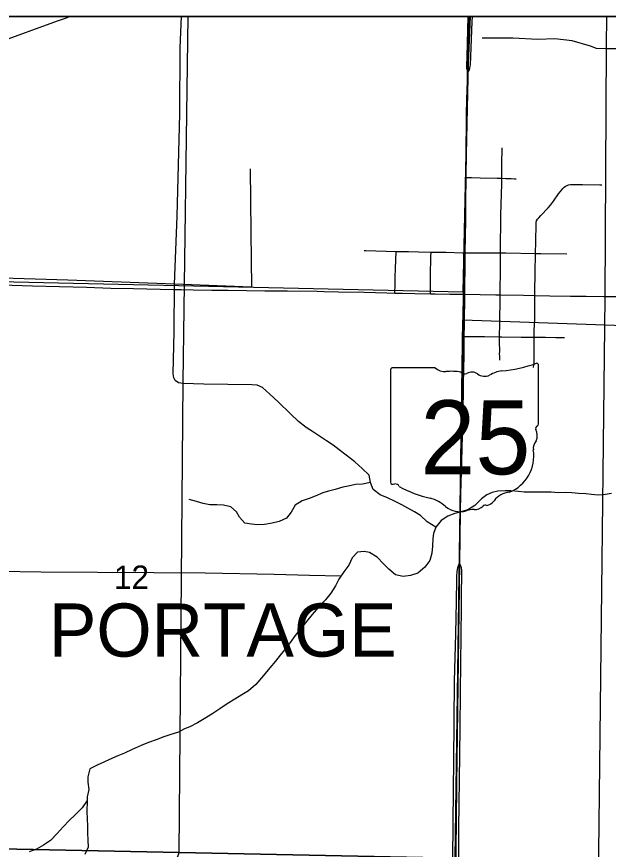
# Model space of a CAD drawing. Extents: x 0 to 39.4, y 0 to 22.
# Drawn here: x 4.625 to 5.679, y 19.416 to 20.9 of the extents above; entities that cross this region are included whole.
import ezdxf

# ---------------------------------------------------------------- set-up
doc = ezdxf.new("R2010")
doc.units = 0
for name, color, linetype in [('Default', 7, 'Continuous'), ('GM_X_City_Street', 7, 'Continuous'), ('GM_X_Corporation_Text', 7, 'Continuous'), ('GM_X_Interstate_Route', 7, 'Continuous'), ('GM_X_Major_River', 7, 'Continuous'), ('GM_X_Minor_River', 7, 'Continuous'), ('GM_X_Rail_Line', 7, 'Continuous'), ('GM_X_Section', 7, 'Continuous'), ('GM_X_Section_Text', 7, 'Continuous'), ('GM_X_State_Location', 7, 'Continuous'), ('GM_X_State_Route', 7, 'Continuous'), ('GM_X_State_Shield', 7, 'Continuous'), ('GM_X_Township_Road', 7, 'Continuous'), ('SH_Data', 7, 'Continuous')]:
    doc.layers.add(name, color=color, linetype=linetype)

msp = doc.modelspace()

# ---------------------------------------------------------------- linework, layer by layer
at = {"layer": 'Default'}
for points in [[(5.4307, 20.9), (4.4171, 20.9), (4.4054, 20.4323), (5.4199, 20.4099)], [(6.4727, 20.9), (5.4307, 20.9), (5.4199, 20.4099), (5.4196, 20.3595), (6.4661, 20.3227)]]:
    msp.add_lwpolyline(points, close=True, dxfattribs=at)
at = {"layer": 'GM_X_City_Street'}
for points in [[(5.4862, 20.4042), (5.4862, 20.4067), (5.4861, 20.4147), (5.4863, 20.4267), (5.4864, 20.4329), (5.4865, 20.4406), (5.4866, 20.4467), (5.4866, 20.4551), (5.4866, 20.4667), (5.4866, 20.4709), (5.4867, 20.479), (5.4867, 20.4855), (5.4868, 20.4938), (5.4869, 20.5043), (5.4874, 20.5228), (5.4874, 20.529), (5.4874, 20.5382), (5.4875, 20.5411), (5.4875, 20.547), (5.4888, 20.6019), (5.4888, 20.6111), (5.4888, 20.612), (5.4889, 20.6173), (5.4888, 20.6203), (5.4891, 20.6388), (5.4892, 20.646), (5.4893, 20.6573), (5.4894, 20.6663)], [(5.4251, 20.6133), (5.4348, 20.6131), (5.4502, 20.6126), (5.4809, 20.6123), (5.4888, 20.612), (5.4963, 20.6117), (5.5055, 20.6116), (5.5115, 20.6113), (5.5145, 20.6111)], [(5.5479, 20.4032), (5.548, 20.4094), (5.5485, 20.4435), (5.5492, 20.478), (5.5496, 20.4993), (5.5499, 20.5303), (5.5501, 20.5334), (5.5509, 20.5364), (5.5526, 20.539), (5.5546, 20.5413), (5.5587, 20.5459), (5.5717, 20.5592), (5.5756, 20.5639), (5.5813, 20.5712), (5.5901, 20.584), (5.5957, 20.5914), (5.5977, 20.5938), (5.5999, 20.596), (5.6024, 20.5979), (5.6051, 20.5993), (5.608, 20.6003), (5.6111, 20.6008), (5.6173, 20.6012), (5.6328, 20.6012), (5.6638, 20.6004), (5.6669, 20.6004)], [(5.244, 20.4835), (5.247, 20.4835), (5.3007, 20.4818), (5.3073, 20.4817), (5.3225, 20.4815), (5.3407, 20.4812), (5.3629, 20.4806), (5.3669, 20.4806), (5.3897, 20.4801), (5.4189, 20.4794), (5.4236, 20.4793)], [(5.2985, 20.4074), (5.2986, 20.412), (5.2988, 20.418), (5.299, 20.4243), (5.2993, 20.4364), (5.2997, 20.4506), (5.3002, 20.4664), (5.3007, 20.4818)], [(5.3617, 20.4062), (5.3617, 20.4131), (5.3619, 20.4381), (5.3627, 20.4724), (5.3629, 20.4806)], [(5.4236, 20.4793), (5.4518, 20.4792), (5.4709, 20.479), (5.4867, 20.479), (5.4959, 20.4789), (5.5492, 20.478), (5.5583, 20.4778), (5.6047, 20.4774)], [(5.4853, 20.2876), (5.4852, 20.2938), (5.4851, 20.2999), (5.4852, 20.3029), (5.4851, 20.3215), (5.485, 20.327), (5.485, 20.3293), (5.485, 20.3366), (5.4853, 20.3458), (5.4854, 20.3581), (5.4855, 20.3643), (5.4856, 20.3674), (5.486, 20.3859), (5.4862, 20.4042)], [(5.5455, 20.2746), (5.5462, 20.2795), (5.5465, 20.2838), (5.5467, 20.2872), (5.5467, 20.2942), (5.5467, 20.3096), (5.5467, 20.322), (5.5466, 20.3287), (5.5467, 20.3318), (5.5468, 20.3404), (5.5475, 20.3622), (5.5476, 20.3715), (5.5479, 20.4032)], [(5.4217, 20.33), (5.4294, 20.3301), (5.4397, 20.3301), (5.4582, 20.3298), (5.485, 20.3293), (5.4888, 20.3293), (5.5233, 20.3287), (5.5386, 20.3287), (5.5466, 20.3287), (5.5559, 20.3287), (5.5667, 20.3286), (5.5853, 20.3285), (5.5915, 20.3284), (5.6006, 20.3285)]]:
    msp.add_lwpolyline(points, dxfattribs=at)
at = {"layer": 'GM_X_Interstate_Route'}
for points in [[(5.4067, 19.4006), (5.4136, 19.9268), (5.4146, 20.0173), (5.4153, 20.0495), (5.4169, 20.1081), (5.4194, 20.1983), (5.42, 20.2356), (5.4203, 20.2505), (5.4205, 20.2661), (5.4211, 20.3031), (5.4214, 20.3225), (5.4215, 20.3305), (5.4218, 20.3506), (5.4224, 20.4059), (5.4227, 20.4226), (5.423, 20.4505), (5.4233, 20.4799), (5.424, 20.5376), (5.4244, 20.5624), (5.4245, 20.5749), (5.4248, 20.6091), (5.4249, 20.6139), (5.4251, 20.6246), (5.4253, 20.6478), (5.4255, 20.6629), (5.4256, 20.6744), (5.4259, 20.6992), (5.4261, 20.7149), (5.4263, 20.7332), (5.4265, 20.7451), (5.4267, 20.7523), (5.4286, 20.8019), (5.4327, 20.9), (2.1, 20.9)], [(8.9, 20.9), (5.4327, 20.9), (5.4286, 20.8019), (5.4267, 20.7523), (5.4265, 20.7451), (5.4263, 20.7332), (5.4261, 20.7149), (5.4259, 20.6992), (5.4256, 20.6744), (5.4255, 20.6629), (5.4253, 20.6478), (5.4251, 20.6246), (5.4249, 20.6139), (5.4248, 20.6091), (5.4245, 20.5749), (5.4244, 20.5624), (5.424, 20.5376), (5.4233, 20.4799), (5.423, 20.4505), (5.4227, 20.4226), (5.4224, 20.4059), (5.4218, 20.3506), (5.4215, 20.3305), (5.4214, 20.3225), (5.4211, 20.3031), (5.4205, 20.2661), (5.4203, 20.2505), (5.42, 20.2356), (5.4194, 20.1983), (5.4169, 20.1081), (5.4153, 20.0495), (5.4146, 20.0173), (5.4136, 19.9268), (5.4067, 19.4006)]]:
    msp.add_lwpolyline(points, dxfattribs=at)
at = {"layer": 'GM_X_Major_River'}
for points in [[(5.6841, 20.0502), (5.6701, 20.0479), (5.6606, 20.0476), (5.6485, 20.0484), (5.6386, 20.0495), (5.6253, 20.0503), (5.6139, 20.0515), (5.6022, 20.0523), (5.59, 20.0516), (5.5768, 20.0524), (5.5665, 20.0528), (5.5532, 20.0528), (5.5434, 20.0525), (5.529, 20.0525), (5.5187, 20.0541), (5.5051, 20.0552), (5.4952, 20.0553), (5.4819, 20.0545), (5.4717, 20.0519), (5.4622, 20.0478), (5.4526, 20.0406), (5.4409, 20.0288), (5.4283, 20.0213), (5.4161, 20.0175), (5.4051, 20.0149), (5.3926, 20.01), (5.3812, 20.0024), (5.3717, 19.9903), (5.3671, 19.9793), (5.3659, 19.9698), (5.3655, 19.9565), (5.3643, 19.944), (5.3609, 19.9311), (5.3517, 19.919), (5.3392, 19.9084), (5.3262, 19.9042), (5.3133, 19.9024), (5.2997, 19.9051), (5.2876, 19.9154), (5.2785, 19.9249), (5.2668, 19.9367), (5.2535, 19.9451), (5.244, 19.947), (5.2319, 19.9455), (5.2224, 19.9357), (5.2166, 19.9224), (5.2075, 19.9107), (5.1987, 19.8974), (5.193, 19.8856), (5.1842, 19.8727), (5.1747, 19.861), (5.1618, 19.8474), (5.1515, 19.8349), (5.1412, 19.822), (5.1313, 19.8099), (5.121, 19.7973), (5.1119, 19.7848), (5.105, 19.775), (5.0943, 19.7621), (5.086, 19.7515), (5.0757, 19.7394), (5.0643, 19.7257), (5.0509, 19.7102), (5.038, 19.6985), (5.0258, 19.6913), (5.0133, 19.6837), (4.9996, 19.6754), (4.9867, 19.6663), (4.9745, 19.658), (4.9619, 19.6505), (4.9467, 19.6418), (4.9331, 19.6346), (4.9236, 19.6308), (4.9129, 19.6248), (4.8996, 19.621), (4.8871, 19.6165), (4.8734, 19.6112), (4.8597, 19.6067), (4.8464, 19.6014), (4.8309, 19.5943), (4.8168, 19.5875), (4.805, 19.5826), (4.7902, 19.5765), (4.7803, 19.5716), (4.7682, 19.566)], [(4.7682, 19.566), (4.7553, 19.5595), (4.7518, 19.5455), (4.7518, 19.536), (4.7536, 19.5227), (4.7505, 19.5098), (4.7505, 19.503)], [(4.7505, 19.503), (4.7418, 19.4901), (4.7284, 19.4772), (4.7189, 19.4681), (4.7075, 19.4564), (4.6972, 19.4443), (4.685, 19.4321), (4.6725, 19.4234), (4.6603, 19.4166), (4.647, 19.4117)]]:
    msp.add_lwpolyline(points, dxfattribs=at)
at = {"layer": 'GM_X_Minor_River'}
for points in [[(5.0439, 20.2442), (4.9581, 20.2449), (4.9217, 20.2461), (4.913, 20.2477), (4.9073, 20.2519), (4.9047, 20.2561), (4.9039, 20.2633), (4.9057, 20.3389), (4.9063, 20.4236), (4.9105, 20.5443), (4.9156, 20.727), (4.9164, 20.8444), (4.9186, 20.9)], [(6.291, 20.8217), (6.1449, 20.8264), (5.9954, 20.8329), (5.8941, 20.8354), (5.8209, 20.8376), (5.7754, 20.8392), (5.7655, 20.8427), (5.756, 20.8465), (5.7405, 20.8492), (5.7276, 20.8488), (5.7097, 20.8455), (5.6961, 20.8429), (5.6767, 20.8429), (5.6574, 20.843), (5.6471, 20.8472), (5.6142, 20.8568), (5.5831, 20.8607), (5.5531, 20.8592), (5.5083, 20.8616), (5.4541, 20.8614)], [(5.0405, 20.629), (5.0417, 20.5162), (5.0429, 20.4182), (4.9063, 20.4236), (4.7159, 20.4302), (4.5213, 20.4361), (4.4146, 20.4383), (4.3289, 20.4412), (4.1931, 20.4443), (4.1506, 20.4456), (3.8975, 20.4498), (3.7617, 20.4536), (3.6141, 20.4571), (3.4491, 20.4655), (3.4017, 20.4657)], [(5.3717, 19.9903), (5.3561, 19.9998), (5.344, 20.0109), (5.3334, 20.0174), (5.3213, 20.0243), (5.3107, 20.03), (5.2978, 20.0365), (5.2853, 20.0426), (5.2721, 20.048), (5.26, 20.0575), (5.2551, 20.0697), (5.2528, 20.083), (5.24, 20.0951), (5.2271, 20.1066), (5.212, 20.1184), (5.1991, 20.1283), (5.1889, 20.1363), (5.1768, 20.1443), (5.1533, 20.1596), (5.1404, 20.1676), (5.1268, 20.1787), (5.1124, 20.192), (5.0908, 20.2137), (5.0761, 20.2274), (5.0628, 20.2389), (5.0532, 20.2436), (5.0439, 20.2442)], [(2.8819, 20.2127), (2.8805, 20.1337), (2.8805, 20.03), (2.8792, 19.9628), (2.9205, 19.9619), (3.0951, 19.9588), (3.2157, 19.955), (3.3064, 19.9524), (3.3716, 19.9492), (3.4706, 19.947), (3.655, 19.9389), (3.8234, 19.9323), (4.0109, 19.9245), (4.1395, 19.9203), (4.3235, 19.916), (4.4418, 19.9145), (4.6683, 19.9107), (4.8691, 19.9098), (4.9609, 19.9087), (5.0834, 19.9068), (5.1464, 19.9048), (5.2027, 19.9034)], [(5.2551, 20.0697), (5.241, 20.067), (5.2281, 20.0663), (5.2156, 20.0633), (5.2057, 20.0614), (5.1924, 20.0577), (5.1803, 20.0547), (5.17, 20.0513), (5.1563, 20.0456), (5.1461, 20.0415), (5.1332, 20.0374), (5.121, 20.0294), (5.1137, 20.0173), (5.1054, 20.0063), (5.0924, 20.0006), (5.0799, 19.9976), (5.0666, 19.995), (5.0537, 19.9947), (5.0431, 19.9955), (5.031, 19.9974), (5.0215, 20.0081), (5.0166, 20.0176), (5.0064, 20.0267), (4.9935, 20.0294), (4.9817, 20.0302), (4.9692, 20.0302), (4.9571, 20.0326), (4.945, 20.036), (4.9321, 20.0398)], [(4.7505, 19.503), (4.7501, 19.4832), (4.7504, 19.4711), (4.7511, 19.457), (4.7511, 19.4456), (4.7514, 19.4327), (4.7522, 19.4198), (4.7464, 19.4069)]]:
    msp.add_lwpolyline(points, dxfattribs=at)
at = {"layer": 'GM_X_Rail_Line'}
for points in [[(4.9299, 20.9), (4.9207, 20.2492), (4.9136, 19.4102), (4.7206, 18.8553), (4.6861, 18.7801), (4.66, 18.7382), (4.6327, 18.7007), (4.4144, 18.4874), (4.369, 18.4419), (4.3263, 18.3862), (4.2933, 18.3287), (4.2793, 18.2799), (4.2724, 18.2363), (4.2649, 18.1427), (4.2497, 17.419), (4.2467, 16.9177), (4.235, 16.198), (4.2196, 15.6628), (4.2092, 15.5913), (4.1936, 15.4989), (4.1313, 15.1291), (4.1146, 15.0383)], [(5.3695, 15.387), (5.386, 16.3854), (5.3967, 18.3974), (5.4127, 19.8659), (5.4216, 20.4077), (5.4296, 20.9)], [(5.6115, 14.1), (5.6226, 15.3413), (5.6228, 15.3801), (5.635, 16.7601), (5.6441, 17.4388), (5.6457, 18.044), (5.6539, 18.4301), (5.6611, 19.3588), (5.6728, 20.3992), (5.6755, 20.8483), (5.6758, 20.9)]]:
    msp.add_lwpolyline(points, dxfattribs=at)
at = {"layer": 'GM_X_Section'}
for points in [[(4.4054, 20.4323), (5.4199, 20.4099), (5.4196, 20.3595), (5.4059, 19.4006), (4.394, 19.4215)], [(5.4196, 20.3595), (6.4661, 20.3227), (6.4302, 19.3208), (5.4065, 19.3604), (5.4059, 19.4006)], [(4.394, 19.4215), (5.4059, 19.4006), (5.4065, 19.3604), (5.3953, 18.3924), (4.3942, 18.4237)]]:
    msp.add_lwpolyline(points, close=True, dxfattribs=at)
at = {"layer": 'GM_X_State_Route'}
for p, q in [((5.4089, 19.8967), (5.409, 19.9007)), ((5.4081, 19.8579), (5.4089, 19.8967))]:
    msp.add_line(p, q, dxfattribs=at)
for points in [[(5.4289, 20.8014), (5.4273, 20.805), (5.4267, 20.8078), (5.4264, 20.8115), (5.4271, 20.8287), (5.4289, 20.9)], [(5.4289, 20.8014), (5.4306, 20.804), (5.4321, 20.8082), (5.4327, 20.8118), (5.433, 20.8144), (5.4364, 20.8909), (5.4367, 20.9)], [(5.4248, 20.5774), (5.425, 20.6085), (5.4251, 20.6133), (5.4253, 20.624), (5.4256, 20.6473), (5.4257, 20.6623), (5.4258, 20.6738), (5.4261, 20.6986), (5.4263, 20.7143), (5.4265, 20.7326), (5.4267, 20.7446), (5.4269, 20.7517), (5.4289, 20.8014)], [(5.4237, 20.4913), (5.4243, 20.537), (5.4246, 20.5619), (5.4248, 20.5744), (5.4248, 20.5774)], [(5.4226, 20.4053), (5.4229, 20.422), (5.4232, 20.45), (5.4236, 20.4793), (5.4237, 20.4913)], [(5.4206, 20.2538), (5.4208, 20.2656), (5.4213, 20.3025), (5.4216, 20.3219), (5.4217, 20.33), (5.4221, 20.3501), (5.4226, 20.4053)], [(5.419, 20.174), (5.4197, 20.1978), (5.4203, 20.235), (5.4205, 20.2499), (5.4206, 20.2538)], [(5.4138, 19.9262), (5.4149, 20.0167), (5.4155, 20.049), (5.4171, 20.1075), (5.419, 20.174)], [(5.409, 19.9007), (5.4091, 19.9043), (5.4095, 19.9101), (5.4101, 19.9154), (5.4112, 19.9203), (5.4138, 19.9262)], [(5.4175, 19.9007), (5.4177, 19.9098), (5.4175, 19.9138), (5.4169, 19.9182), (5.416, 19.9209), (5.4138, 19.9262)], [(5.4174, 19.8533), (5.4174, 19.8765), (5.4175, 19.9007)], [(5.4018, 19.4001), (5.4024, 19.4611), (5.403, 19.5232), (5.4036, 19.573), (5.4049, 19.7159), (5.4068, 19.8003), (5.4081, 19.8579)], [(5.4148, 19.6354), (5.4154, 19.6928), (5.4161, 19.7519), (5.4167, 19.7923), (5.4174, 19.8533)], [(5.4123, 19.4), (5.4126, 19.4193), (5.4127, 19.4535), (5.4142, 19.584), (5.4148, 19.6354)]]:
    msp.add_lwpolyline(points, dxfattribs=at)
at = {"layer": 'GM_X_State_Shield'}
for p, q in [((5.2906, 20.2705), (5.2906, 20.0704)), ((5.3704, 20.274), (5.2932, 20.274)), ((5.5543, 20.1742), (5.5543, 20.2789)), ((5.5542, 20.1743), (5.5543, 20.1742))]:
    msp.add_line(p, q, dxfattribs=at)
for centre, radius, start, end in [((5.2936, 20.2709), 0.00305, 98.1301, 188.1301), ((5.3888, 20.2972), 0.0296, 231.6195, 271.1119), ((5.4603, 20.5468), 0.2796, 275.8445, 288.9065), ((5.5513, 20.2794), 0.00294, 351.8621, 97.738), ((5.3986, 20.1616), 0.1064, 80.4867, 94.9883), ((5.4228, 20.272), 0.00855, 219.7921, 297.1024), ((5.4353, 20.2488), 0.0178, 54.4667, 119.1411), ((5.4582, 20.2806), 0.0214, 233.8562, 294.8282), ((5.496, 20.2128), 0.0563, 97.3462, 120.7689), ((5.5536, 20.1665), 0.00454, 107.944, 210.337), ((5.5511, 20.1738), 0.00314, 289.6038, 7.7341), ((5.5247, 20.1533), 0.0273, 340.033, 23.6496), ((5.5648, 20.1304), 0.0198, 136.8065, 186.9296), ((5.476, 20.1171), 0.0699, 292.3089, 8.9858), ((5.2936, 20.07), 0.00308, 171.9584, 258.3066), ((5.2941, 20.0904), 0.0235, 267.339, 280.6039), ((5.2989, 20.0588), 0.00848, 29.7484, 93.2717), ((5.406, 20.2386), 0.2019, 240.4129, 257.1985), ((5.5055, 20.0142), 0.0383, 94.4031, 142.5768), ((5.3458, 19.9805), 0.0632, 47.1842, 75.836), ((5.457, 20.051), 0.0226, 282.8732, 323.2771), ((5.4141, 20.0579), 0.0401, 230.7004, 286.2918), ((5.4373, 19.9887), 0.0329, 85.6951, 111.2099), ((5.4402, 20.0429), 0.0214, 268.777, 315.5493), ((5.4595, 20.0235), 0.00601, 65.7517, 132.6484)]:
    msp.add_arc(centre, radius, start, end, dxfattribs=at)
at = {"layer": 'GM_X_Township_Road'}
msp.add_line((4.9112, 20.4137), (4.9179, 20.4137), dxfattribs=at)
for points in [[(4.416, 20.7972), (4.4418, 20.8048), (4.4895, 20.8191), (4.5131, 20.8267), (4.5543, 20.8409), (4.5895, 20.8532), (4.6975, 20.8926), (4.7122, 20.8976), (4.7188, 20.9)], [(4.411, 20.4277), (4.4448, 20.4267), (4.5069, 20.425), (4.6529, 20.4205), (4.7492, 20.4177), (4.7926, 20.4164), (4.833, 20.4154), (4.9045, 20.4137), (4.9112, 20.4137)], [(4.9179, 20.4137), (4.9395, 20.4135), (4.9726, 20.4129)], [(4.9726, 20.4129), (5.0016, 20.4124), (5.0669, 20.4116), (5.1073, 20.4114), (5.1601, 20.4107), (5.1725, 20.4104), (5.1973, 20.4098), (5.2438, 20.4088), (5.2842, 20.4078), (5.2985, 20.4074)], [(5.2985, 20.4074), (5.3122, 20.4071), (5.3339, 20.4067), (5.3617, 20.4062)], [(5.3617, 20.4062), (5.3705, 20.406), (5.3961, 20.4056), (5.4226, 20.4053)], [(5.4226, 20.4053), (5.4782, 20.4044), (5.4862, 20.4042)], [(5.4862, 20.4042), (5.5278, 20.4036), (5.5479, 20.4032)], [(5.5479, 20.4032), (5.5743, 20.4028), (5.6115, 20.4022), (5.6394, 20.4019), (5.6704, 20.4014), (5.6983, 20.4011), (5.7324, 20.4002), (5.7541, 20.3999), (5.7976, 20.3994), (5.8472, 20.3987), (5.903, 20.398), (5.934, 20.3972), (5.9528, 20.3969)]]:
    msp.add_lwpolyline(points, dxfattribs=at)
at = {"layer": 'SH_Data'}
msp.add_line((2.1, 20.9), (8.9, 20.9), dxfattribs=at)

# ---------------------------------------------------------------- texts
at = {"layer": 'GM_X_Corporation_Text'}
msp.add_text('PORTAGE', height=0.0947, rotation=0, dxfattribs=at).set_placement((4.6824, 19.7596))
at = {"layer": 'GM_X_Section_Text'}
msp.add_text('12', height=0.04186, rotation=0, dxfattribs=at).set_placement((4.7984, 19.8801))
at = {"layer": 'GM_X_State_Location'}
for s, p in [('s', (5.4195, 20.1571)), ('r', (5.4194, 20.1571))]:
    msp.add_text(s, height=0.000189, dxfattribs=at).set_placement(p)
msp.add_text('25', height=0.000189, rotation=0, dxfattribs=at).set_placement((5.3718, 20.1434))
at = {"layer": 'GM_X_State_Shield'}
msp.add_text('25', height=0.13184, dxfattribs=at).set_placement((5.3439, 20.0845))

doc.saveas('drawing.dxf')
